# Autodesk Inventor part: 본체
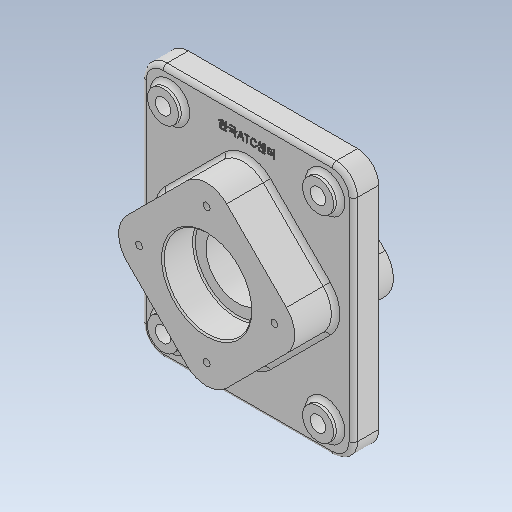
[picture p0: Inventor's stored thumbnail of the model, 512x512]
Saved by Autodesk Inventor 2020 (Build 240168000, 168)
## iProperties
Created: 2021-07
Part Number: 본체
Material: 일반
Document SubType Name: Modeling
Designer: Owner
Mass: 807.977 g
Surface Area: 961.758 cm^2
Volume: 807.977 cm^3
Density: 1 g/cm^3
Appearance: 기본값
Author: Owner
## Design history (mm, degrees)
sketch "스케치1"
  geometry: L1 (75, 90)-(-75, 90); L2 (-75, 90)-(-75, -90); L3 (-75, -90)-(75, -90); L4 (75, -90)-(75, 90); L5 (75, 90)-(-75, -90); L6 (-75, 90)-(75, -90); 1 further point
  constraints: 12 end point, 2 midpoint, 2 parallel, 1 horizontal, 1 perpendicular
  dimensions: "d0" = 150 distance of L3.end L2.end; "d1" = 180 distance of L2.end L1.end
extrude "돌출1" new body sketch "스케치1" stored distance "d2" = 18; taper "d3" = 0 deg
sketch "스케치2"
  geometry: L1 (0, -70.711)-(-70.711, 0); L2 (-70.711, 0)-(0, 70.711); L3 (0, 70.711)-(70.711, 0); L4 (70.711, 0)-(0, -70.711); L5 (0, -70.711)-(0, 70.711); L6 (-70.711, 0)-(70.711, 0); 2 further points
  constraints: 12 end point, 3 midpoint, 2 parallel, 1 horizontal alignment, 1 perpendicular, 1 vertical alignment
  dimensions: "d4" = 100 distance of L1.end L2.end
extrude "돌출2" join sketch "스케치2" distance "d5" = 29; taper "d6" = 0 deg
sketch "스케치3"
  geometry: L1 (0, 70.711)-(-70.711, 0) reference; L2 (70.711, 0)-(0, 70.711) reference; L3 (-70.711, 0)-(0, -70.711) reference; L4 (0, -70.711)-(70.711, 0) reference; L5 (-75, -90)-(75, -90) reference; L6 (75, -90)-(75, 90) reference; L7 (75, 90)-(-75, 90) reference; L8 (-75, 90)-(-75, -90) reference; 1 further point
extrude "돌출3" join sketch "스케치3" distance "d7" = 23; taper "d8" = 0 deg
fillet "모깎기1" dims "d9" = 20
fillet "모깎기2" dims "d10" = 20
sketch "스케치4"
  geometry: 2 further points
  constraints: 1 vertical alignment
  dimensions: "d11" = 48 distance of point (0, 0) point (0, 48)
hole "구멍1" sketch "스케치4" at (0, 48) diameter "d12" = 4.917; stored, may be unused: countersink angle "d16" = 90 deg, drill point angle "d18" = 118 deg; dims "d13" = 10, "d14" = 4, "d15" = 2, "d17" = 13
sketch "스케치5"
  geometry: C1 r 31 at (0, 0); 1 further point
  constraints: 1 centre point, 1 coincident
  dimensions: "d19" = 62 diameter of C1
extrude "돌출4" cut sketch "스케치5" distance "d20" = 22; taper "d21" = 0 deg
sketch "스케치6"
  geometry: C1 r 31 at (0, 0); 1 further point
  constraints: 1 centre point, 1 coincident
  dimensions: "d22" = 62 diameter of C1
extrude "돌출5" cut sketch "스케치6" distance "d23" = 22; taper "d24" = 0 deg
sketch "스케치7"
  geometry: C1 r 31 at (0, 0) reference; C2 r 22.5 at (0, 0); 1 further point
  constraints: 1 centre point, 1 coincident
  dimensions: "d25" = 45 diameter of C2
extrude "돌출6" cut sketch "스케치7" extent not by distance; stored distance "d26" = 22; taper "d27" = 0 deg
sketch "스케치8"
  geometry: 2 further points
  constraints: 1 vertical alignment
  dimensions: "d31" = 48 distance of point (0, 0) point (0, 48)
hole "구멍2" sketch "스케치8" at (0, 48) diameter "d32" = 4.917; stored, may be unused: countersink angle "d36" = 90 deg, drill point angle "d38" = 118 deg; dims "d33" = 10, "d34" = 4, "d35" = 2, "d37" = 13
fillet "모깎기3" dims "d42" = 15
sketch "스케치9"
  geometry: L1 (75, -75)-(75, 75) reference; L2 (60, 90)-(-60, 90) reference; L3 (-75, 75)-(-75, -75) reference; L4 (-60, -90)-(60, -90) reference; L5 (-14.142, -56.569)-(-56.569, -14.142) reference; L6 (-56.569, 14.142)-(-14.142, 56.569) reference; L7 (14.142, 56.569)-(56.569, 14.142) reference; L8 (56.569, -14.142)-(14.142, -56.569) reference; L9 (14.142, -56.569)-(56.569, -14.142) reference; L10 (56.569, 14.142)-(14.142, 56.569) reference; L11 (-14.142, 56.569)-(-56.569, 14.142) reference; L12 (-56.569, -14.142)-(-14.142, -56.569) reference; C1 r 2.458 at (-48, 0) reference; C2 r 2.458 at (0, -48) reference; C3 r 2.458 at (48, 0) reference; C4 r 2.458 at (0, 48) reference; C5 r 31 at (0, 0) reference; C6 r 11 at (-55, -70); C7 r 11 at (-55, 70); C8 r 11 at (55, -70); C9 r 11 at (55, 70); A1 r 15 centre (60, -75) between (60, -90) and (75, -75) reference; A2 r 15 centre (60, 75) between (75, 75) and (60, 90) reference; A3 r 15 centre (-60, 75) between (-60, 90) and (-75, 75) reference; A4 r 15 centre (-60, -75) between (-75, -75) and (-60, -90) reference; A5 r 20 centre (-42.426, 0) between (-56.569, 14.142) and (-56.569, -14.142) reference; A6 r 20 centre (0, 42.426) between (14.142, 56.569) and (-14.142, 56.569) reference; A7 r 20 centre (42.426, 0) between (56.569, -14.142) and (56.569, 14.142) reference; A8 r 20 centre (0, -42.426) between (-14.142, -56.569) and (14.142, -56.569) reference; A9 r 20 centre (0, -42.426) between (-14.142, -56.569) and (14.142, -56.569) reference; A10 r 20 centre (42.426, 0) between (56.569, -14.142) and (56.569, 14.142) reference; A11 r 20 centre (0, 42.426) between (14.142, 56.569) and (-14.142, 56.569) reference; A12 r 20 centre (-42.426, 0) between (-56.569, 14.142) and (-56.569, -14.142) reference; 1 further point
  constraints: 4 centre point
  dimensions: "d43" = 22 diameter of C6; "d44" = 22 diameter of C7; "d45" = 22 diameter of C8; "d46" = 22 diameter of C9; "d47" = 140 distance of C6.centre C7.centre; "d48" = 70 vertical distance of point (0, 0) C7.centre; "d49" = 110 distance of C8.centre C6.centre; "d50" = 55 horizontal distance of point (0, 0) C6.centre; "d51" = 110 distance of C9.centre C7.centre; "d52" = 55 horizontal distance of point (0, 0) C7.centre; "d53" = 140 distance of C8.centre C9.centre; "d54" = 70 vertical distance of point (0, 0) C9.centre
extrude "돌출7" join sketch "스케치9" distance "d55" = 5; taper "d56" = 0 deg
sketch "스케치10"
  geometry: C1 r 11 at (0, 0) reference; 2 further points
  constraints: 1 coincident
hole "구멍3" sketch "스케치10" at (0, 0) diameter "d57" = 11; stored, may be unused: countersink angle "d61" = 90 deg, drill point angle "d63" = 118 deg; dims "d58" = 10, "d59" = 4, "d60" = 2, "d62" = 13
fillet "모깎기4" dims "d64" = 1
chamfer "모따기1" distance "d65" = 1; stored, may be unused: second distance "d66" = 2, angle "d67" = 45 deg
fillet "모깎기6" dims "d69" = 3
sketch "스케치12"
  geometry: L1 (75, -75)-(75, 75) reference; L2 (60, 90)-(-60, 90) reference; L3 (-75, 75)-(-75, -75) reference; L4 (-60, -90)-(60, -90) reference; L5 (-14.142, -56.569)-(-56.569, -14.142) reference; L6 (-56.569, 14.142)-(-14.142, 56.569) reference; L7 (14.142, 56.569)-(56.569, 14.142) reference; L8 (56.569, -14.142)-(14.142, -56.569) reference; C1 r 14 at (55, -70) reference; C2 r 14 at (-55, 70) reference; C3 r 14 at (55, 70) reference; C4 r 14 at (-55, -70) reference; A1 r 15 centre (60, -75) between (60, -90) and (75, -75) reference; A2 r 15 centre (60, 75) between (75, 75) and (60, 90) reference; A3 r 15 centre (-60, 75) between (-60, 90) and (-75, 75) reference; A4 r 15 centre (-60, -75) between (-75, -75) and (-60, -90) reference; A5 r 20 centre (-42.426, 0) between (-56.569, 14.142) and (-56.569, -14.142) reference; A6 r 20 centre (0, 42.426) between (14.142, 56.569) and (-14.142, 56.569) reference; A7 r 20 centre (42.426, 0) between (56.569, -14.142) and (56.569, 14.142) reference; A8 r 20 centre (0, -42.426) between (-14.142, -56.569) and (14.142, -56.569) reference; 2 further points
  constraints: 1 vertical alignment, 1 other
  dimensions: "d70" = 15 distance from line of L2 point (0, 75)
feature "엠보싱1" sketch "스케치12" dims "d0" = 150, "d1" = 180, "d71" = 0.5, "d72" = 0
fillet "모깎기7" dims "d73" = 3
fillet "모깎기8" dims "d74" = 3
node "솔리드1"
pattern_circular "원형 패턴1" dims angle "d29" = 360 deg
pattern_circular "원형 패턴2" dims angle "d40" = 360 deg
mirror "미러2"
mirror "미러3"
node "투영된 루프1"
node "투영된 루프2"
node "투영된 루프3"
node "투영된 루프4"
feature "A9D066F2-1C7D-4E18-AEED-F7BC21143FA4" dims "d57" = 11, "d58" = 10, "d59" = 4, "d60" = 2, "d61" = 90 deg, "d62" = 13, "d63" = 118 deg
